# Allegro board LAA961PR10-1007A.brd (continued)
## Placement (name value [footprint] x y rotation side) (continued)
T21  PAD~D  [TPC12]  138.6 75.1 0 top
T22  PAD~D  [TPC12]  141.75 79.26 0 top
T27  PAD~D  [TPC12]  143.95 73.08 0 top
T28  PAD~D  [TPC12]  93.28 65.8 180 bottom
T29  PAD~D  [TPC12]  93.33 68.08 180 bottom
T30  PAD~D  [TPC12]  95.37 88.76 180 bottom
T31  PAD~D  [TPC12]  96.45 87.99 180 bottom
T33  PAD~D  [TPC12]  108.45 96.29 0 top
T34  PAD~D  [TPC12]  107.18 92.71 0 top
T35  PAD~D  [TPC12]  97.09 81.84 0 top
T74  PAD~D  [TPC12]  92.91 81.75 0 top
T75  PAD~D  [TPC12]  98.36 81.83 0 top
T76  PAD~D  [TPC12]  95.21 83.28 0 top
T77  PAD~D  [TPC12]  94.98 81.74 0 top
T88  PAD~D  [TPC12]  207.84 119.45 90 top
T89  PAD~D  [TPC12]  206.48 119.46 90 top
T96  PAD~D  [TPC12]  182.32 109.01 180 top
T97  PAD~D  [TPC12]  173.08 98.35 180 top
T98  PAD~D  [TPC12]  175.87 104.84 0 top
T99  PAD~D  [TPC12]  175.44 98.09 0 top
T108  PAD~D  [TPC12]  146.75 109.91 180 bottom
T109  PAD~D  [TPC12]  134.5 84.01 0 top
TL1  MHPC_NS692417  [MHPC_NS692417_24P]  268.27 131.63 0 bottom
UA1  -  [ALC3235-CG_MQFN48_6X6]  203.43 72.97 270 top
UC1  BDW-ULT-DDR3L_BGA1168  [BDW-ULT-DDR3L_BGA_1168P-T]  138.82 90.26 0 bottom
UC2  -  [W25Q64FVSSIQ_SO8]  182.19 76.25 270 bottom
UC3  -  [W25Q32FVSSIQ_SO8]  191.91 76.25 270 bottom
UC4  -  [74AHC1G09GW_TSSOP5]  162.06 85.54 270 bottom
UC5  TC7SH08FU_SSOP5~D  [TC7SH08FU_SSOP5]  161.8 80.68 180 bottom
UC6  TC7SH08FU_SSOP5~D  [TC7SH08FU_SSOP5]  159.33 80.26 180 bottom
UC7  -  [74CBTLV3126BQ_DHVQFN14_2P5X3]  63.6 67.13 90 top
UC8  -  [74AUP1G07GW_TSSOP5]  76 78.75 0 top
UD1  -  [74AUP1G07GW_TSSOP5]  96.6 13.14 180 top
UE1  ECE5048-LZY_DQFN132_11X11~D  [ECE5048-LZY_DQFN132_11X11]  176.99 105.34 270 top
UE2  -  [MEC5085-LZY_DQFN132_11X11]  211.07 88.25 90 top
UI2  SY6288D10CAC_MSOP8  [G547I2P81U_MSOP8]  240.06 121.66 90 bottom
UI3  -  [TPS2544RTER_WQFN16_3X3]  59.65 118.7 0 top
UI4  -  [PI3USB3102ZLEX_TQFN32_6X3]  127.73 128.96 0 top
UI5  -  [NX3DV221GM_XQFN10U10_2X1P55]  129.87 125.52 270 bottom
UI7  -  [PS8713BTQFN24GTR2_TQFN24_4X4]  222.6 82.96 270 top
UL1  WGI218LM-QQ89-B0_QFN48_6X6~D  [WGI217LM-QPN9-A2_QFN48_6X6]  206.15 112.27 0 top
UL2  -  [TC7SH08FU_SSOP5]  211.62 120.58 0 top
UL3  -  [TPS22966DPUR_SON14_2X3]  194.37 109.58 270 top
UL4  PI3L720ZHEX_TQFN42_9X3P5~D  [PI3L720ZHEX_TQFN42_9X3P5]  220.22 122.6 180 bottom
UN1  -  [LNG3DMTR_LGA16_3X3]  223.36 115.36 90 top
UR1  -  [OZ777FJ2LN_QFN48_6X6]  24.49 21.89 180 top
UV7  -  [PS8339BQFN56GTR2-A0_QFN56_7X7]  119.86 119.58 270 top
UV8  VMM3320BJGR_BGA168  [VMM3320BJGR_BGA_168P-NH]  155.72 108.16 90 bottom
UV9  W25X10CVSNIG_SO8  [W25X10BVSNIG_SO8]  151.92 97.84 90 bottom
UV10  -  [AP2330W-7_SC59-3]  99.63 126.61 90 bottom
UV11  PI3C3125LEX_TSSOP14~D  [PI3C3125LEX_TSSOP14]  133.83 121.17 90 bottom
UV12  PI3C3125LEX_TSSOP14~D  [PI3C3125LEX_TSSOP14]  159.79 107.09 0 bottom
UV13  -  [TPS22966DPUR_SON14_2X3]  140.15 101.2 180 bottom
UV24  -  [AP2821KTR-G1_SOT23-5]  77.39 122.96 270 top
UV501  -  [AP2337SA-7_SOT23-3]  253.2 126.48 90 top
UV502  PI3C3125LEX_TSSOP14~D  [PI3C3125LEX_TSSOP14]  236.54 119.82 0 top
UV600  -  [PS8338BQFN60GTR-A0_QFN60_5X9]  138.53 120.71 270 top
UZ1  AT97SC3205_TSSOP28~D  [AT97SC3205_TSSOP28]  182.18 61.1 270 top
UZ2  -  [TPS22966DPUR_SON14_2X3]  191 44.24 0 top
UZ5  -  [RT9818A-44GU3_SC70-3]  190.68 82.89 180 top
UZ6  TC7SH08FU_SSOP5~D  [TC7SH08FU_SSOP5]  186 88.42 90 top
UZ7  -  [TPS22966DPUR_SON14_2X3]  132.01 98.71 270 top
UZ8  -  [TPS22966DPUR_SON14_2X3]  202.26 33.33 90 top
UZ9  -  [TPS22966DPUR_SON14_2X3]  58 59.53 90 top
UZ10  TC7SH08FU_SSOP5~D  [TC7SH08FU_SSOP5]  186.3 115.69 0 top
UZ11  -  [TC7SH08FU_SSOP5]  176.11 111.12 270 top
YC1  32.768KHZ_12.5PF_9H03220008  [Y_9H03220008_2P]  143.85 62.09 0 bottom
YC2  24MHZ_12PF_X3G024000DC1H  [Y_X3G024000DC1H_4P]  127.34 99.03 90 top
YE1  32.768KHZ_12.5PF_Q13FC135000040  [Y_Q13FC135000040_2P]  207.65 83.22 270 top
YL1  25MHZ_18PF_7V25000034  [Y_7V25000034_4P]  209.71 104.34 90 top
YV2  27MHZ_12PF_X1E000021042600  [Y_X1E000021042600_4P]  141.76 103.92 90 bottom

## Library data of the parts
C33 PC5 PC10 PC101 PC102 PC200 PC201 PC205 PC303 PC305-PC308 PC401 PC404 PC515-PC518 PC704-PC709 PC714-PC717 PC723-PC725 PC807 PC900-PC904 PC913-PC917 = C_0805
C42 C43 C319 CA5-CA8 CA11 CA17 CA19 CA22-CA24 CA27 CA28 CA30 CA33 CA35 CA41 CA45 CA47 CA50 CC3 CC14 CC15 CC22 CC25 CC48 CC50 CC52 CC57 CC68-CC73 CC78 CC80 CC82 CC83 CC97 CC100 CC101 CD31 CD59 CD63 CD64 CE3-CE6 CE10-CE20 CE22-CE30 CE34-CE40 CE44-CE46 CI3-CI5 CI10 CI12 CI19 CI27-CI35 CI38 CI414-CI419 CL1-CL3 CL5 CL6 CL8-CL11 CL13-CL15 CL18 CL19 CL23-CL27 CN2 CN13-CN16 CN35-CN38 CR2-CR4 CR6 CR8 CR10 CR13 CR15 CR17 CR19 CR21-CR27 CR31 CR35 CV1-CV6 CV8 CV10 CV11 CV24 CV30 CV60-CV62 CV66 CV69 CV71-CV80 CV83-CV86 CV88 CV89 CV91-CV93 CV95-CV100 CV102-CV111 CV113-CV124 CV145-CV150 CV152 CV153 CV156 CV157 CV501-CV513 CV518 CV600-CV613 CZ1 CZ2 CZ4-CZ7 CZ9-CZ18 CZ20-CZ25 CZ27-CZ37 CZ39-CZ53 CZ55 CZ56 CZ58-CZ60 CZ62-CZ66 CZ68 PC3 PC4 PC105 PC106 PC203 PC206 PC212-PC215 PC300 PC304 PC311 PC400 PC402 PC403 PC501-PC504 PC506 PC511-PC514 PC520 PC521 PC702 PC703 PC711 PC713 PC718 PC719 PC726-PC728 PC732 PC737 PC741 PC805 PC809 PC810 PC817 = C_0402
C263 = C_0402: room: SIM
C294-C316 CE8 CE9 = C_0402: room: DOCK
C317 C318 CE7 = C_0603: room: DOCK
CA9 CA10 CA16 CA18 CA25 CA26 CA29 CA31 CA43 CA44 CA46 CA48 CA49 CA51-CA53 CC23 CC55 CC79 CC84 CC85 CD62 CE21 CE31 CE32 CI11 CI13 CI420 CL4 CL7 CL12 CL16 CL17 CL20 CL21 CN1 CR1 CR7 CR9 CR14 CR18 CR34 CV7 CV9 CV12 CV27 CV82 CV87 CV90 CV94 CV101 CZ19 CZ38 CZ54 PC1 PC9 PC11 PC100 PC109-PC111 PC114 PC117-PC119 PC204 PC208 PC209 PC211 PC301 PC302 PC309 PC310 PC500 PC505 PC507-PC510 PC700 PC701 PC710 PC712 PC721 PC722 PC729 PC813 PC815 PC816 = C_0603
CC1 CC2 CC4-CC13 CC17-CC21 CC24 CC26-CC28 CC35 CC37 CC40 CC43 CC44 CC49 CC53 CC54 CC58 CC59 CC61 CC65 CC66 = C_0402: room: CPU
CC29-CC34 CC36 CC47 CC51 CC56 CC60 CC62-CC64 = C_0603: room: CPU
CC39 = C_D2: room: CPU
CC41 = C_D3
CC42 = C_D3: room: CPU
CC67 = C_1206: room: CPU
CC77 CC81 CI1 CI8 = C_1206
CD1-CD11 CD21-CD27 CD30 CD32-CD44 CD54-CD58 CD60 = C_0402: room: MEMORY
CD12-CD19 CD28 CD29 CD45-CD52 CD61 = C_0603: room: MEMORY
CD20 CD53 = C_D3: room: MEMORY
CE1 = C_0603: room: EDP
CE2 = C_0402: room: EDP
CL22 = C_1808
CMOS1 = SHORTPADS: User Part Number: PART#; room: CPU
CZ57 = C_B2
D19 = RB751S40T1G_SOD523-2: room: DOCK
D20 = L30ESD24VC3-2_SOT23-3: room: DOCK
DA4 DA5 DE1 DZ1-DZ6 = RB751S40T1G_SOD523-2
DA6 DA7 = L03ESDL5V0CC3-2_SOT23-3
DI1 DI6 = L05ESDL5V0NA-4_SLP2510P8-10-9
DI2 DI3 DV4 PD5 = AZC199-02SPR7G_SOT23-3
DV1-DV3 PD815 PD817 = BAT54CW_SOT323-3
FD1-FD4 = FIDUCIAL_C40M80: room: LED
H1-H6 H12-H16 = H_2P8: room: LED
H7 = H_3P8
H8-H10 = H_3P8: room: LED
H11 H27 = H_2P8
H18 H19 = H_3P3
H20 = H_2P1N
H21 H22 = H_3P1: room: LED
H23 = H_2P1X2P6
JANT1 = ACES_50208-00801-003_8P
JAPS1 = ACES_50506-01841-P01_18P-NPM
JDEG1 = ACES_50521-01041-P01_10P: room: KBC
JDIMM1 JDIMM2 = BELLW_80001-1021_204P: room: MEMORY
JDOCK1 = JAE_WD2F144WB7-DT_144P-T: room: DOCK
JEDP1 = ACES_50398-04041-001_40P
JFAN1 = ACES_50271-0040N-001_4P: room: ETY-ROOM
JHDMI1 = LCN_AUF05-1922S10-0019_19P-T: room: ETY-ROOM
JIO1 = ACES_50506-03041-P01_30P: room: ETY-ROOM
JKBTP1 = ACES_50506-01641-P01_16P: room: ETY-ROOM
JLED1 = E-T_4260K-Q06N-23L_6P
JLOM1 = SANTA_130456-511_13P-T: room: LOM
JLPDE1 = HB_A531015-SCHR21_10P
JMDP1 = FOX_3V112M1-RA4A2-7H_20P
JNGFF1 = BELLW_80148-3221_67P-T
JNGFF2 = BELLW_80149-3221_67P
JRTC1 = TYCO_2-1775293-2_2P
JSATA1 = E-T_0870K-F20C-22L_20P: room: HDD
JSD1 = T-SOL_156-2000302608_19P_NR-S: room: OZ777
JSIM1 = T-SOL_159-1000302602_10P-T: room: ETY-ROOM
JSPI1 = E-T_6700K-Y20N-00L_20P
JSPK1 = E-T_4280K-F04N-05L_4P: room: ETY-ROOM
JTAG1 = SHORTPADS: User Part Number: PART#; room: KBC
JUSB1 JUSB2 = TAITW_PUBAU4-09FLBS1FF4H0_9P: room: ETY-ROOM
JUSH1 = E-T_6705K-Y20N-00L_20P: room: ETY-ROOM
JXDP1 = SAMTE_BSH-030-01-L-D-A_60P: room: CPU
LA5 = MURAT_BLM15PX600SN1D_2P
LA6-LA9 = MURAT_BLM15PX330SN1D_2P
LC1-LC5 = MURAT_LQM2MPN2R2NG0L_2P: room: CPU
LED5 LED6 = LED_LTW-193ZDS5_2P: room: ETY-ROOM
LED7 = LED_LTW-295DSKS-5A_4P: room: ETY-ROOM
LI1-LI4 LI8 LI9 LV3 LV6 LV10 LV12 LV27 LZ1 = MURAT_DLW21HN900HQ2L_4P
LL1 = TAIYO_BRC2012T4R7MD_2P
LV1 = MURAT_BLM15BB221SN1D_2P
LV22-LV25 = MURAT_BLM15PX181SN1D_2P
PBATT1 = ALLTO_C144LS-109A9-L_9P-T
PC113 PC115 = C_APXK6R3ARA221MF451
PC207 PC966 = C_D2
PC519 = C_D
PD1 PD2 = TVNST52302AB0_SOT523-3
PD3 = BAS40-05W_SC70-3
PD4 = RB751V-40_SOD323-2
PD702 PD704 PD705 PD813 = SDMK0340L-7-F_SOD323-2
PD800 PD808 = PDS5100H-13_POWERDI5-3
PH500 PH501 PR1 PR2 PR7-PR15 PR17 PR18 PR100-PR102 PR104-PR107 PR114 PR201 PR205 PR206 PR209 PR303 PR306-PR310 PR315 PR400-PR403 PR500-PR516 PR518 PR521 PR523-PR525 PR527-PR529 PR535 PR703 PR706 PR707 PR710 PR711 PR713 PR715 PR722 PR725 PR729 PR737 PR738 PR740 PR745 PR788 PR799 PR810 PR813-PR816 PR818 PR819 PR822 PR826-PR830 PR844 PR846 PR858 PR863 PR864 PR874 R6 R41 R273 RA5-RA9 RA12-RA14 RA17 RA18 RA21 RA24-RA32 RA38 RA44 RC21 RC27 RC34 RC62 RC66 RC68 RC80 RC92 RC98 RC121 RC123 RC124 RC126 RC128 RC130 RC132 RC136 RC139 RC141 RC142 RC156 RC164 RC171 RC174 RC176 RC178-RC180 RC184-RC189 RC191 RC192 RC194 RC195 RC197-RC199 RC201 RC202 RC204 RC207-RC209 RC211 RC213 RC216 RC224-RC229 RC231 RC247 RC300 RC302-RC305 RD2 RD4 RD9 RD12-RD14 RD18-RD25 RE8-RE12 RE17 RE20 RE21 RE24-RE27 RE31 RE33 RE35-RE37 RE42 RE43 RE48 RE51 RE55-RE58 RE60 RE62-RE75 RE77-RE79 RE81-RE83 RE85-RE88 RE274 RE276 RE277 RE280 RE281 RE283 RE284 RI4 RI13 RI14 RI16 RI18-RI20 RI22-RI25 RI34-RI38 RL1 RL2 RL4-RL6 RL9 RL11-RL20 RL29 RL30 RN1-RN7 RR1 RR2 RR5 RR6 RR8 RR11 RR15 RV1-RV9 RV14 RV15 RV50-RV52 RV54-RV58 RV60-RV68 RV73-RV91 RV100 RV501-RV505 RV507-RV509 RV516-RV519 RV550 RV551 RV554 RV555 RV600-RV620 RV701 RV702 RZ5 RZ8-RZ10 RZ14-RZ16 RZ18 RZ19 RZ21 RZ22 RZ24-RZ41 RZ43 RZ44 RZ56 = R_0402
PJP1 PJP13 PJP21 PJP22 PJP32 PJP100-PJP102 PJP203 PJP204 PJP300 PJP500 = JUMP_43X118
PJP5 = JUMP_43X39: room: TPM
PJP6 = JUMP_43X79: room: SIO
PJP9 PJP200 PJP302 = JUMP_43X79
PJP10-PJP12 PJP14-PJP17 PJP19 PJP23-PJP29 PJP36 PJP51 PJP66 PJP201 PJP202 PJP400 PJP401 PJP701 = JUMP_43X39
PJP700 = JUMP_43X118-NPM
PJPDC1 = ACES_50299-0050N-001_5P
PL1 PL2 PL4 = TAIYO_FBMJ4516HS720NT_2P
PL3 = MURAT_BLM15AG102SN1D_2P
PL100 = L_5X5X3_M_2P-NPM
PL101 PL102 PL200 = PANAS_ETQP3W2R2WFN_2P
PL301 PL700 = L_5X5X3_M_2P
PL500 = PANAS_ETQP4LR15AFM_4P
PL501 = FBMA-L11-453215800LMA90T_2P-NPM
PL701 = TOKO_FDVE1040-H-3R3M-P3_2P
PQ1 = FDN338P_NL_SOT23-3
PQ2 = FDV301N-G_SOT23-3
PQ3 = MMST3904-7-F_SOT323-3
PQ4 PQ826 = FDMC6679AZ_MLP8-5
PQ6 = IMD2AT-108_SC74-6
PQ100 PQ101 PQ200 = SIS412DN-T1-GE3_POWERPAK8-5
PQ102 PQ103 PQ201 = SI7716ADN-T1-GE3_POWERPAK8-5
PQ700 PQ800 = SI4835DDY-T1-GE3_SO8
PQ701 PQ702 PQ814 = NTR4502PT1G_SOT23-3
PQ703 = NTGD4161PT1G_TSOP6
PQ705 = AON6970_DFN5X6D-8-7
PQ712 PQ816 PQ832 = DMN65D8LW-7_SOT323-3
PQ806 PQ813 PQ817 = DMN65D8LDW-7_SOT363-6
PQ810 PQ815 = FDS6679AZ-G_SO8
PQ829 = SI2301CDS-T1-GE3_SOT23-3
PR6 PR103 PR108 PR113 PR207 PR210 PR313 PR520 PR531 PR532 PR534 PR536 PR539 PR700 PR702 PR704 PR705 PR709 PR714 PR716-PR718 PR720 PR728 PR743 PR811 PR812 PR842 PR843 PR845 PR848 PR850 PR851 PR853-PR855 PR857 PR859 PR895 RA35-RA37 RA45 RC26 RC32 RC65 RC77 RC212 RC217 RC219 RC301 RD15 RD16 RD27 RD28 RE32 RE61 RE275 RE279 RE282 RL3 RL7 RL10 RR3 RR4 RZ17 RZ42 RZ50 RZ51 RZ57 = R0402_0OHM
PR16 PR835 = R_0805
PR109 PR110 PR200 PR202 PR204 PR312 PR517 PR519 PR526 PR712 PR723 PR831 PR832 PR838 PR847 PR860 RC196 RL21-RL28 RZ46 = R_0603
PR111 PR112 PR203 PR305 PR522 PR708 PR726 RZ52 = R_1206
PR701 PR721 = R_1206_4P-D
PRP2 RPC1-RPC12 RPC14-RPC21 RPE2-RPE10 RPV1 RPV2 = RP_0804_8P4R
PT1-PT3 T8 T9 T88 T89 T96 T99 T108 T109 = TPC12
PU1 = TS5A63157DCKR_SC70-6
PU100 = TPS51285BRUKR_QFN20_3X3
PU200 = RT8207MZQW_WQFN20_3X3
PU300 = SYX198DQNC_QFN10_3X3
PU400 = APL5930KAI-TRG_SO8
PU500 = TPS51622RSM_QFN32_4X4
PU501 = CSD97374CQ4M_SON8_3P5X4P5
PU700 = BQ24715URUYR_WQFN28_4X4
PU800 = CD3301RHHR_QFN36_6X6
PU804 PU806 UC5 UC6 UL2 UZ6 UZ10 UZ11 = TC7SH08FU_SSOP5
QA1 QV2 QV7 QV9 QV10 QV501 QV502 = L2N7002WT1G_SC-70-3
QA2 QA3 QE2 QL1 QL2 QN1 QV700 QZ2 QZ3 QZ5 QZ7 QZ10 QZ11 QZ14 = DMN66D0LDW-7_SOT363-6
QC1 = DMN66D0LDW-7_SOT363-6: room: CPU
QD1 = L2N7002WT1G_SC-70-3: room: MEMORY
QE3-QE7 = MMBT3904WT1G_SC70-3
QV1 = AO6405_TSOP6
QV8 QZ1 = LP2301ALT1G_SOT23-3
QZ4 QZ9 QZ12 = DDTA114EUA-7-F_SOT323-3
QZ6 = SI3456DDV-T1-GE3_TSOP6
R252-R268 R271 R272 RE5 = R_0402: room: DOCK
RA3 RA4 RL8 RZ47 RZ53 = R0603_0OHM
RA39 = R0805_0OHM
RC1 RC2 RC7-RC11 RC17-RC20 RC22 RC23 RC25 RC29 RC31 RC33 RC38 RC55 RC61 RC63 RC67 RC69 RC70 RC72 RC74 RC78 RC79 RC81 RC82 RC91 RC95 RC99 RC102 RC103 RC106 RC109 RC112-RC120 RC122 RC125 RC127 RC129 RC131 RC133 RC140 RC149 RC152 RC153 RC155 RC158 RC160 RC163 RC175 RC183 RC190 RC193 RC218 RC230 RC240-RC243 RC245 = R_0402: room: CPU
RC4 RC30 RC35 RC50 RC87-RC89 RC161 = R0402_0OHM: room: CPU
RD3 = R0402_0OHM: room: MEMORY
RD5-RD7 RD10 RD11 = R_0402: room: MEMORY
ST1-ST3 = CLIP_C5P5
SW1 = SW_SS3-CMFTQR9_3P
SW2 = SW_SKRBAAE010_4P
T10-T16 T21 T22 T27-T31 T33-T35 T74-T77 = TPC12: room: CPU
T97 T98 = TPC12: room: SIO
TL1 = MHPC_NS692417_24P
UA1 = ALC3235-CG_MQFN48_6X6
UC1 = BDW-ULT-DDR3L_BGA_1168P-T: room: CPU
UC2 = W25Q64FVSSIQ_SO8: room: CPU
UC3 = W25Q32FVSSIQ_SO8: room: CPU
UC4 = 74AHC1G09GW_TSSOP5: room: CPU
UC7 = 74CBTLV3126BQ_DHVQFN14_2P5X3
UC8 UD1 = 74AUP1G07GW_TSSOP5
UE1 = ECE5048-LZY_DQFN132_11X11
UE2 = MEC5085-LZY_DQFN132_11X11
UI2 = G547I2P81U_MSOP8
UI3 = TPS2544RTER_WQFN16_3X3
UI4 = PI3USB3102ZLEX_TQFN32_6X3
UI5 = NX3DV221GM_XQFN10U10_2X1P55
UI7 = PS8713BTQFN24GTR2_TQFN24_4X4
UL1 = WGI217LM-QPN9-A2_QFN48_6X6
UL3 UV13 UZ2 UZ7-UZ9 = TPS22966DPUR_SON14_2X3
UL4 = PI3L720ZHEX_TQFN42_9X3P5
UN1 = LNG3DMTR_LGA16_3X3
UR1 = OZ777FJ2LN_QFN48_6X6
UV7 = PS8339BQFN56GTR2-A0_QFN56_7X7
UV8 = VMM3320BJGR_BGA_168P-NH
UV9 = W25X10BVSNIG_SO8
UV10 = AP2330W-7_SC59-3
UV11 UV12 UV502 = PI3C3125LEX_TSSOP14
UV24 = AP2821KTR-G1_SOT23-5
UV501 = AP2337SA-7_SOT23-3
UV600 = PS8338BQFN60GTR-A0_QFN60_5X9
UZ1 = AT97SC3205_TSSOP28
UZ5 = RT9818A-44GU3_SC70-3
YC1 = Y_9H03220008_2P: room: CPU
YC2 = Y_X3G024000DC1H_4P: room: CPU
YE1 = Y_Q13FC135000040_2P
YL1 = Y_7V25000034_4P
YV2 = Y_X1E000021042600_4P

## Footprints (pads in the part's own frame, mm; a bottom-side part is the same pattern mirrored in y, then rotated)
74AHC1G09GW_TSSOP5
  oval 0.381x1.346 smd: 1(0,0) 2(0.65,0) 3(1.3,0) 4(1.3,1.79) 5(0,1.79)
74AUP1G07GW_TSSOP5
  oval 0.381x1.346 smd: 1(0,0) 2(0.65,0) 3(1.3,0) 4(1.3,1.79) 5(0,1.79)
74CBTLV3126BQ_DHVQFN14_2P5X3
  oval 1.041x0.254 smd: 1(0,0) 7(2.95,0) 8(2.95,0.5) 14(0,0.5)
  oval 0.254x1.041 smd: 2(0.475,-0.975) 3(0.975,-0.975) 4(1.475,-0.975) 5(1.975,-0.975) 6(2.475,-0.975) 9(2.475,1.475) 10(1.975,1.475) 11(1.475,1.475) 12(0.975,1.475) 13(0.475,1.475)
  rect 1.499x0.991 smd: 15(1.475,0.25)
ACES_50208-00801-003_8P
  oval 0.508x0.991 smd: 1(0,0) 2(-0.8,0) 3(-1.6,0) 4(-2.4,0) 5(-3.2,0) 6(-4,0) 7(-4.8,0) 8(-5.6,0)
  rect 1.194x1.702 smd: 9(1.3,-1.95) 10(-6.9,-1.95)
ACES_50271-0040N-001_4P
  oval 0.787x1.6 smd: 1(0,0) 2(-1.25,0) 3(-2.5,0) 4(-3.75,0)
  rect 2.108x2.997 smd: 5(2.55,-2.9) 6(-6.3,-2.9)
ACES_50299-0050N-001_5P
  round 1.803 hole 1.803 unplated: (-0.2,5.15) (8.2,5.15)
  oval 0.889x2.311 smd: 1(0,0) 2(2,0) 3(4,0) 4(6,0) 5(8,0)
ACES_50398-04041-001_40P
  oval 0.254x1.295 smd: 1(0,0) 2(0.5,0) 3(1,0) 4(1.5,0) 5(2,0) 6(2.5,0) 7(3,0) 8(3.5,0) 9(4,0) 10(4.5,0) 11(5,0) 12(5.5,0) 13(6,0) 14(6.5,0) 15(7,0) 16(7.5,0) 17(8,0) 18(8.5,0) 19(9,0) 20(9.5,0) 21(10,0) 22(10.5,0) 23(11,0) 24(11.5,0) 25(12,0) 26(12.5,0) 27(13,0) 28(13.5,0) 29(14,0) 30(14.5,0) 31(15,0) 32(15.5,0) 33(16,0) 34(16.5,0) 35(17,0) 36(17.5,0) 37(18,0) 38(18.5,0) 39(19,0) 40(19.5,0)
  rect 1.194x3.2 smd: 41(-2.4,1.95) 45(21.9,1.95)
  rect 2.311x1.295 smd: 42(0.85,3.9) 43(9.75,3.9) 44(18.65,3.9)
ACES_50506-01641-P01_16P
  oval 0.305x0.889 smd: 1(0,0) 2(0.5,0) 3(1,0) 4(1.5,0) 5(2,0) 6(2.5,0) 7(3,0) 8(3.5,0) 9(4,0) 10(4.5,0) 11(5,0) 12(5.5,0) 13(6,0) 14(6.5,0) 15(7,0) 16(7.5,0)
  rect 0.991x2.007 smd: 17(9.6,-3.05) 18(-2.1,-3.05)
ACES_50506-01841-P01_18P-NPM
  oval 0.305x0.889 smd: 1(0,0) 2(0.5,0) 3(1,0) 4(1.5,0) 5(2,0) 6(2.5,0) 7(3,0) 8(3.5,0) 9(4,0) 10(4.5,0) 11(5,0) 12(5.5,0) 13(6,0) 14(6.5,0) 15(7,0) 16(7.5,0) 17(8,0) 18(8.5,0)
  rect 0.991x2.007 smd: 19(-2.1,-3.05) 20(10.6,-3.05)
ACES_50506-03041-P01_30P
  oval 0.305x0.889 smd: 1(0,0) 2(0.5,0) 3(1,0) 4(1.5,0) 5(2,0) 6(2.5,0) 7(3,0) 8(3.5,0) 9(4,0) 10(4.5,0) 11(5,0) 12(5.5,0) 13(6,0) 14(6.5,0) 15(7,0) 16(7.5,0) 17(8,0) 18(8.5,0) 19(9,0) 20(9.5,0) 21(10,0) 22(10.5,0) 23(11,0) 24(11.5,0) 25(12,0) 26(12.5,0) 27(13,0) 28(13.5,0) 29(14,0) 30(14.5,0)
  rect 0.991x2.007 smd: 31(-2.1,-3.05) 32(16.6,-3.05)
ACES_50521-01041-P01_10P
  oval 0.305x0.787 smd: 1(0,0) 2(0.5,0) 3(1,0) 4(1.5,0) 5(2,0) 6(2.5,0) 7(3,0) 8(3.5,0) 9(4,0) 10(4.5,0)
  rect 0.406x0.787 smd: 11(-1,-2.5) 12(5.5,-2.5)
ALC3235-CG_MQFN48_6X6
  oval 0.203x0.889 smd: 1(0,0) 2(0.4,0) 3(0.8,0) 4(1.2,0) 5(1.6,0) 6(2,0) 7(2.4,0) 8(2.8,0) 9(3.2,0) 10(3.6,0) 11(4,0) 12(4.4,0) 25(4.4,6.1) 26(4,6.1) 27(3.6,6.1) 28(3.2,6.1) 29(2.8,6.1) 30(2.4,6.1) 31(2,6.1) 32(1.6,6.1) 33(1.2,6.1) 34(0.8,6.1) 35(0.4,6.1) 36(0,6.1)
  oval 0.889x0.203 smd: 13(5.25,0.85) 14(5.25,1.25) 15(5.25,1.65) 16(5.25,2.05) 17(5.25,2.45) 18(5.25,2.85) 19(5.25,3.25) 20(5.25,3.65) 21(5.25,4.05) 22(5.25,4.45) 23(5.25,4.85) 24(5.25,5.25) 37(-0.85,5.25) 38(-0.85,4.85) 39(-0.85,4.45) 40(-0.85,4.05) 41(-0.85,3.65) 42(-0.85,3.25) 43(-0.85,2.85) 44(-0.85,2.45) 45(-0.85,2.05) 46(-0.85,1.65) 47(-0.85,1.25) 48(-0.85,0.85)
  rect 4.394x4.394 smd: 49(2.2,3.05)
ALLTO_C144LS-109A9-L_9P-T
  round 1.803 hole 1.194: 1(0,0) 2(2,0) 3(4,0) 4(6,0) 5(8,0) 6(10,0) 7(12,0) 8(14,0) 9(16,0)
  oval 1.6x3.404 hole 0.991x2.794: 10(19.125,0.25) 11(-3.125,0.25)
AO6405_TSOP6
  oval 0.508x1.473 smd: 1(0,0) 2(0.95,0) 3(1.9,0) 4(1.9,2.35) 5(0.95,2.35) 6(0,2.35)
AON6970_DFN5X6D-8-7
  oval 0.66x0.635 smd: 1(0,0) 3(3.81,5.67) 4(2.54,5.67) 5(1.27,5.67) 6(0,5.67)
  custom 0.485x0.485 smd: 2(1.905,0.655)
  rect 3.988x2.667 smd: 7(1.905,3.62)
AP2330W-7_SC59-3
  oval 0.787x0.991 smd: 1(0,0) 2(-0.95,-2.4) 3(0.95,-2.4)
AP2337SA-7_SOT23-3
  oval 1.016x1.524 smd: 1(0,0) 2(0.965,2.083) 3(-0.965,2.083)
AP2821KTR-G1_SOT23-5
  oval 0.508x0.787 smd: 1(0,0) 2(0.95,0) 3(1.9,0) 4(1.9,2.4) 5(0,2.4)
APL5930KAI-TRG_SO8
  oval 0.635x1.854 smd: 1(0,0) 2(1.27,0) 3(2.54,0) 4(3.81,0) 5(3.81,5.165) 6(2.54,5.165) 7(1.27,5.165) 8(0,5.165)
  rect 2.87x2.489 smd: 9(1.905,2.582)
AT97SC3205_TSSOP28
  oval 0.381x1.626 smd: 1(0,0) 2(0.65,0) 3(1.3,0) 4(1.95,0) 5(2.6,0) 6(3.25,0) 7(3.9,0) 8(4.55,0) 9(5.2,0) 10(5.85,0) 11(6.5,0) 12(7.15,0) 13(7.8,0) 14(8.45,0) 15(8.45,5.8) 16(7.8,5.8) 17(7.15,5.8) 18(6.5,5.8) 19(5.85,5.8) 20(5.2,5.8) 21(4.55,5.8) 22(3.9,5.8) 23(3.25,5.8) 24(2.6,5.8) 25(1.95,5.8) 26(1.3,5.8) 27(0.65,5.8) 28(0,5.8)
AZC199-02SPR7G_SOT23-3
  oval 1.016x1.524 smd: 1(0,0) 2(0.965,2.083) 3(-0.965,2.083)
BAS40-05W_SC70-3
  oval 0.508x0.559 smd: 1(0,0) 2(-0.65,-1.85) 3(0.65,-1.85)
BAT54CW_SOT323-3
  oval 0.61x0.559 smd: 1(0,0) 2(-0.65,-1.85) 3(0.65,-1.85)
BDW-ULT-DDR3L_BGA_1168P-T
  round 0.508 smd: A3(-1.137,0) A62(-38.036,0) AW1(0,22.042) AW63(-38.628,22.057) AY2(-0.543,22.628) AY62(-38.062,22.628) B2(-0.508,0.508) B63(-38.628,0.592) C1(0,1.137)
  round 0.381 smd: A4(-1.894,0) A5(-2.554,0) A6(-3.75,0) A59(-35.9,0) A60(-36.726,0) A61(-37.386,0) AA9(-5.032,11.576) AA21(-11.688,11.489) AA23(-13.115,11.489) AA58(-35.377,11.33) AB10(-5.476,12.053) AB20(-11.18,11.896) AB21(-11.688,12.302) AB22(-12.607,11.896) AB23(-13.115,12.302) AB57(-35.057,11.98) AC9(-5.032,12.529) AC20(-11.18,12.709) AC22(-12.607,12.709) AC58(-35.377,12.63) AD10(-5.476,13.005) AD21(-11.688,13.115) AD23(-13.115,13.115) AD57(-35.057,13.28) AE9(-5.032,13.481) AE10(-5.476,13.958) AE20(-11.18,13.521) AE21(-11.688,13.928) AE22(-12.607,13.521) AE23(-13.115,13.928) AE58(-35.377,13.931) AF9(-5.032,14.434) AF11(-6.059,14.282) AF12(-6.872,14.282) AF14(-7.685,14.282) AF15(-8.497,14.282) AF17(-9.31,14.282) AF18(-10.123,14.282) AF20(-10.936,14.282) AF22(-12.607,14.334) AG10(-5.653,14.79) AG11(-6.465,14.79) AG13(-7.278,14.79) AG14(-8.091,14.79) AG16(-8.904,14.79) AG17(-9.717,14.79) AG19(-10.529,14.79) AG20(-11.342,14.79) AG23(-13.115,14.741) AG57(-35.057,14.581) AG58(-35.692,15.009) AH22(-12.607,15.147) AH24(-13.92,15.289) AH26(-15.22,15.289) AH28(-16.521,15.289) AH30(-17.821,15.289) AH32(-19.122,15.289) AH34(-20.422,15.289) AH36(-21.723,15.289) AH38(-23.023,15.289) AH40(-24.324,15.289) AH42(-25.624,15.289) AH44(-26.925,15.289) AH46(-28.225,15.289) AH49(-29.526,15.289) AH51(-30.826,15.289) AH53(-32.127,15.289) AH55(-33.427,15.289) AH57(-34.728,15.289) AJ23(-13.115,15.553) AJ25(-14.57,15.614) AJ27(-15.871,15.614) AJ29(-17.171,15.614) AJ31(-18.472,15.614) AJ33(-19.772,15.614) AJ35(-21.073,15.614) AJ37(-22.373,15.614) AJ39(-23.674,15.614) AJ41(-24.974,15.614) AJ43(-26.275,15.614) AJ45(-27.575,15.614) AJ47(-28.875,15.614) AJ50(-30.176,15.614) AJ52(-31.476,15.614) AJ54(-32.777,15.614) AJ56(-34.077,15.614) AJ58(-35.378,15.614) AT1(0,19.997) AT63(-38.628,19.848) AU1(0,20.657) AU63(-38.628,20.673) AV1(0,21.318) AV2(-0.66,21.308) AV62(-37.978,21.318) AV63(-38.628,21.333) AW2(-0.66,21.968) AW3(-1.321,21.968) AW61(-37.328,21.978) AW62(-37.978,21.978) AY3(-1.267,22.628) AY4(-1.928,22.628) AY5(-2.588,22.628) AY59(-36.088,22.628) AY60(-36.748,22.628) AY61(-37.409,22.628) B3(-1.259,0.65) B61(-37.315,0.66) B62(-37.978,0.724) C2(-0.65,1.259) C62(-37.978,1.384) C63(-38.628,1.316) D1(0,1.861) D63(-38.628,1.976) E1(0,2.522) E23(-13.333,2.601) E25(-14.714,2.601) E27(-15.84,2.601) E29(-17.221,2.601) E31(-18.348,2.601) E33(-19.729,2.601) E35(-20.855,2.601) E37(-22.236,2.601) E39(-23.363,2.601) E41(-24.744,2.601) E43(-25.87,2.601) E45(-27.251,2.601) E47(-28.378,2.601) E49(-29.759,2.601) E51(-30.885,2.601) E53(-32.266,2.601) E55(-33.393,2.601) E57(-34.774,2.601) E63(-38.628,2.647) F1(0,3.436) F22(-12.717,3.058) F24(-14.023,3.126) F26(-15.277,3.126) F28(-16.531,3.126) F30(-17.785,3.126) F32(-19.038,3.126) F34(-20.292,3.126) F36(-21.546,3.126) F38(-22.8,3.126) F40(-24.053,3.126) F42(-25.307,3.126) F44(-26.561,3.126) F46(-27.815,3.126) F48(-29.068,3.126) F50(-30.322,3.126) F52(-31.576,3.126) F54(-32.83,3.126) F56(-34.083,3.126) F58(-35.377,3.126) G22(-12.607,3.768) G23(-13.333,3.451) G25(-14.714,3.451) G27(-15.84,3.451) G29(-17.221,3.451) G31(-18.348,3.451) G33(-19.729,3.451) G35(-20.855,3.451) G37(-22.236,3.451) G39(-23.363,3.451) G41(-24.744,3.451) G43(-25.87,3.451) G45(-27.251,3.451) G47(-28.378,3.451) G49(-29.759,3.451) G51(-30.885,3.451) G53(-32.266,3.451) G55(-33.393,3.451) G57(-34.774,3.451) H22(-12.607,4.581) H23(-13.115,4.174) H57(-35.057,4.101) J22(-12.607,5.393) J23(-13.115,4.987) J58(-35.377,4.827) K9(-5.032,5.861) K10(-5.935,5.7) K12(-6.888,5.7) K14(-7.84,5.7) K16(-8.793,5.7) K18(-9.745,5.7) K19(-10.698,5.7) K21(-11.65,5.7) K23(-13.115,5.8) K57(-35.057,5.478) L10(-5.476,6.338) L11(-6.412,6.144) L13(-7.364,6.144) L15(-8.317,6.144) L17(-9.269,6.144) L18(-10.222,6.144) L20(-11.18,6.206) L22(-12.607,6.206) L58(-35.377,6.128) M9(-5.032,6.814) M20(-11.18,7.019) M21(-11.688,6.613) M22(-12.607,7.019) M23(-13.115,6.613) M57(-35.057,6.778) N10(-5.476,7.29) N21(-11.688,7.425) N23(-13.115,7.425) N58(-35.377,7.428) P9(-5.032,7.766) P20(-11.18,7.832) P22(-12.607,7.832) P57(-35.057,8.078) R10(-5.476,8.243) R20(-11.18,8.645) R21(-11.688,8.238) R22(-12.607,8.645) R23(-13.115,8.238) T9(-5.032,8.719) T21(-11.688,9.051) T23(-13.115,9.051) T58(-35.377,8.729) U9(-5.032,9.671) U10(-5.476,9.195) U20(-11.18,9.457) U22(-12.607,9.457) U57(-35.057,9.379) V10(-5.476,10.148) V21(-11.688,9.864) V23(-13.115,9.864) V58(-35.377,10.029) W9(-5.032,10.624) W20(-11.18,10.27) W21(-11.688,10.677) W22(-12.607,10.27) W23(-13.115,10.677) W57(-35.057,10.679) Y10(-5.476,11.1) Y20(-11.18,11.083) Y22(-12.607,11.083)
  round 0.305 smd: A8(-4.538,0) A9(-5.452,0) A11(-6.367,0) A12(-7.116,0) A14(-8.03,0) A15(-8.945,0) A17(-9.694,0) A18(-10.608,0) A20(-11.523,0) A21(-12.272,0) A23(-13.186,0) A24(-14.023,0.325) A25(-14.714,0) A27(-15.84,0) A28(-16.531,0.325) A29(-17.221,0) A31(-18.348,0) A32(-19.038,0.325) A33(-19.729,0) A35(-20.855,0) A36(-21.546,0.325) A37(-22.236,0) A39(-23.363,0) A40(-24.053,0.325) A41(-24.744,0) A43(-25.87,0) A44(-26.561,0.325) A45(-27.251,0) A47(-28.378,0) A48(-29.068,0.325) A49(-29.759,0) A51(-30.885,0) A52(-31.576,0.325) A53(-32.266,0) A55(-33.393,0) A56(-34.083,0.325) A57(-34.774,0) AA1(0,11.717) AA2(-0.65,11.717) AA3(-1.3,11.678) AA4(-1.951,11.678) AA59(-36.027,11.638) AA60(-36.678,11.638) AA61(-37.328,11.638) AA62(-37.978,11.676) AA63(-38.628,11.676) AB5(-2.637,12.053) AB6(-3.287,12.053) AB7(-3.937,12.053) AB8(-4.587,12.053) AC1(0,12.466) AC2(-0.65,12.466) AC3(-1.3,12.504) AC4(-1.951,12.504) AC59(-36.027,12.464) AC60(-36.678,12.464) AC61(-37.328,12.464) AC62(-37.978,12.426) AC63(-38.628,12.426) AD1(0,13.215) AD2(-0.65,13.215) AD3(-1.3,13.177) AD4(-1.951,13.177) AD5(-2.637,13.005) AD6(-3.287,13.005) AD7(-3.937,13.005) AD8(-4.587,13.005) AD59(-36.027,13.137) AD60(-36.678,13.137) AD61(-37.328,13.137) AD62(-37.978,13.175) AD63(-38.628,13.175) AE5(-2.637,13.958) AE6(-3.287,13.958) AE7(-3.937,13.958) AE8(-4.587,13.958) AE59(-36.027,13.962) AE60(-36.678,13.962) AE61(-37.328,13.962) AE62(-37.978,13.924) AE63(-38.628,13.924) AF1(0,13.964) AF2(-0.65,13.964) AF3(-1.3,14.003) AF4(-1.951,14.003) AG1(0,14.714) AG2(-0.65,14.714) AG3(-1.3,14.676) AG4(-1.951,14.676) AG5(-2.637,14.91) AG6(-3.287,14.91) AG7(-3.937,14.91) AG8(-4.587,14.91) AG21(-11.955,15.122) AG60(-36.352,14.602) AG61(-37.003,14.602) AG62(-37.653,14.602) AG63(-38.303,14.602) AH1(0,15.463) AH2(-0.65,15.463) AH3(-1.3,15.501) AH4(-1.951,15.501) AH10(-5.653,15.476) AH11(-6.465,15.476) AH13(-7.278,15.476) AH14(-8.091,15.476) AH16(-8.904,15.476) AH17(-9.717,15.476) AH19(-10.529,15.476) AH20(-11.342,15.476) AH60(-36.678,15.278) AH61(-37.328,15.278) AH62(-37.978,15.278) AH63(-38.628,15.278) AJ5(-2.637,15.863) AJ6(-3.287,15.863) AJ7(-3.937,15.863) AJ8(-4.587,15.863) AJ10(-5.653,16.126) AJ11(-6.465,16.126) AJ13(-7.278,16.126) AJ14(-8.091,16.126) AJ60(-36.352,15.954) AJ61(-37.003,15.954) AJ62(-37.653,15.954) AJ63(-38.303,15.954) AK1(0,16.212) AK2(-0.65,16.212) AK3(-1.3,16.174) AK4(-1.951,16.174) AK8(-4.303,16.451) AK18(-9.848,16.266) AK20(-10.801,16.266) AK21(-11.753,16.266) AK60(-36.678,16.523) AK61(-37.328,16.523) AK62(-37.978,16.629) AK63(-38.628,16.629) AL1(0,16.962) AL2(-0.65,16.962) AL3(-1.3,17) AL4(-1.951,17) AL5(-2.901,16.776) AL7(-3.739,16.776) AL8(-4.303,17.101) AL10(-5.658,16.776) AL11(-6.221,17.101) AL13(-7.576,16.776) AL15(-8.14,17.101) AL17(-9.222,16.583) AL18(-9.848,16.916) AL20(-10.801,16.916) AL21(-11.753,16.916) AL22(-12.706,16.916) AL23(-13.529,16.916) AL25(-14.504,16.916) AL26(-15.456,16.916) AL28(-16.409,16.916) AL29(-17.361,16.916) AL31(-18.26,16.591) AL32(-18.824,16.916) AL33(-19.726,16.916) AL35(-20.729,16.916) AL36(-21.58,16.916) AL38(-22.634,16.916) AL39(-23.542,16.591) AL40(-24.131,16.916) AL42(-24.944,16.916) AL43(-25.897,16.916) AL45(-26.874,16.916) AL46(-27.802,16.916) AL48(-28.856,16.916) AL49(-29.757,16.916) AL51(-30.761,16.916) AL52(-31.583,16.916) AL54(-32.61,16.916) AL55(-33.562,16.916) AL57(-34.509,16.916) AL58(-35.408,16.916) AL60(-36.352,17.169) AL61(-37.003,17.169) AM1(0,17.711) AM2(-0.65,17.711) AM3(-1.3,17.673) AM4(-1.951,17.673) AM5(-2.901,17.426) AM7(-3.739,17.426) AM8(-4.303,17.752) AM10(-5.658,17.426) AM11(-6.221,17.752) AM13(-7.576,17.426) AM15(-8.14,17.752) AM17(-9.222,17.233) AM18(-9.848,17.567) AM20(-10.801,17.567) AM21(-11.753,17.567) AM22(-12.706,17.567) AM23(-13.529,17.567) AM25(-14.504,17.567) AM26(-15.456,17.567) AM28(-16.409,17.567) AM29(-17.361,17.567) AM31(-18.26,17.242) AM32(-18.824,17.567) AM33(-19.726,17.567) AM35(-20.729,17.567) AM36(-21.58,17.567) AM38(-22.634,17.567) AM40(-24.131,17.567) AM42(-24.944,17.567) AM43(-25.897,17.567) AM45(-26.874,17.567) AM46(-27.802,17.567) AM48(-28.856,17.567) AM49(-29.757,17.567) AM51(-30.761,17.567) AM52(-31.583,17.567) AM54(-32.61,17.567) AM55(-33.562,17.567) AM57(-34.509,17.567) AM58(-35.408,17.567) AM60(-36.678,17.816) AM61(-37.328,17.816) AM62(-37.978,17.709) AM63(-38.628,17.709) AN1(0,18.46) AN2(-0.65,18.46) AN3(-1.3,18.498) AN4(-1.951,18.498) AN5(-2.901,18.077) AN7(-3.739,18.077) AN8(-4.303,18.402) AN10(-5.658,18.077) AN11(-6.221,18.402) AN13(-7.576,18.077) AN15(-8.14,18.402) AN17(-9.222,17.883) AN18(-9.848,18.217) AN20(-10.801,18.217) AN21(-11.753,18.217) AN22(-12.706,18.217) AN23(-13.529,18.217) AN25(-14.504,18.217) AN26(-15.456,18.217) AN28(-16.409,18.217) AN29(-17.361,18.217) AN31(-18.26,17.892) AN32(-18.824,18.217) AN33(-19.726,18.217) AN35(-20.729,18.217) AN36(-21.58,18.217) AN38(-22.634,18.217) AN39(-23.542,17.892) AN40(-24.131,18.217) AN42(-24.944,18.217) AN43(-25.897,18.217) AN45(-26.874,18.217) AN46(-27.802,18.217) AN48(-28.856,18.217) AN49(-29.757,18.217) AN51(-30.761,18.217) AN52(-31.583,18.217) AN54(-32.61,18.217) AN55(-33.562,18.217) AN57(-34.509,18.217) AN58(-35.408,18.217) AN60(-36.352,18.385) AN61(-37.003,18.385) AN62(-37.653,18.385) AN63(-38.303,18.385) AP1(0,19.21) AP2(-0.65,19.21) AP3(-1.3,19.171) AP4(-1.951,19.171) AP5(-2.901,18.727) AP7(-3.739,18.727) AP8(-4.303,19.052) AP10(-5.658,18.727) AP11(-6.221,19.052) AP13(-7.576,18.727) AP15(-8.14,19.052) AP17(-9.222,18.533) AP18(-9.848,18.867) AP20(-10.801,18.867) AP21(-11.753,18.867) AP22(-12.706,18.867) AP23(-13.529,18.867) AP25(-14.504,18.867) AP26(-15.456,18.867) AP28(-16.409,18.867) AP29(-17.361,18.867) AP31(-18.26,18.542) AP32(-18.824,18.867) AP33(-19.726,18.867) AP35(-20.729,18.867) AP36(-21.58,18.867) AP38(-22.634,18.867) AP39(-23.542,18.542) AP40(-24.131,18.867) AP42(-24.944,18.867) AP43(-25.897,18.867) AP45(-26.874,18.867) AP46(-27.802,18.867) AP48(-28.856,18.867) AP49(-29.757,18.867) AP51(-30.761,18.867) AP52(-31.583,18.867) AP54(-32.61,18.867) AP55(-33.562,18.867) AP57(-34.509,18.867) AP58(-35.408,18.867) AP60(-36.678,19.06) AP61(-37.328,19.06) AP62(-37.978,19.06) AP63(-38.628,19.06) AR5(-2.901,19.377) AR7(-3.739,19.377) AR8(-4.303,19.702) AR10(-5.658,19.377) AR11(-6.221,19.702) AR13(-7.576,19.377) AR15(-8.14,19.702) AR17(-9.222,19.184) AR18(-9.848,19.517) AR20(-10.801,19.517) AR21(-11.753,19.517) AR22(-12.706,19.517) AR23(-13.529,19.517) AR25(-14.504,19.517) AR26(-15.456,19.517) AR28(-16.409,19.517) AR29(-17.361,19.517) AR31(-18.26,19.192) AR32(-18.824,19.517) AR33(-19.726,19.517) AR35(-20.729,19.517) AR36(-21.58,19.517) AR38(-22.634,19.517) AR39(-23.542,19.192) AR40(-24.131,19.517) AR42(-24.944,19.517) AR43(-25.897,19.517) AR45(-26.874,19.517) AR46(-27.802,19.517) AR48(-28.856,19.517) AR49(-29.757,19.517) AR51(-30.761,19.517) AR52(-31.583,19.517) AR54(-32.61,19.517) AR55(-33.562,19.517) AR57(-34.509,19.517) AR58(-35.408,19.517) AT2(-0.65,19.959) AT3(-1.3,19.997) AT4(-1.951,19.997) AT5(-2.901,20.027) AT7(-3.739,20.027) AT10(-5.658,20.027) AT13(-7.576,20.027) AT35(-20.437,20.22) AT37(-22.011,20.22) AT40(-23.586,20.22) AT42(-25.161,20.22) AT43(-26.736,20.22) AT46(-28.311,20.22) AT49(-29.912,20.248) AT61(-37.003,19.634) AT62(-37.812,19.69) AU2(-0.655,20.647) AU3(-1.315,20.647) AU4(-1.976,20.647) AU6(-3.337,20.678) AU7(-4.163,20.678) AU8(-4.836,20.678) AU10(-5.661,20.678) AU11(-6.335,20.678) AU12(-7.16,20.678) AU14(-7.833,20.678) AU15(-8.659,20.678) AU16(-9.222,20.353) AU17(-9.86,20.678) AU18(-10.536,20.353) AU19(-11.105,20.678) AU20(-11.751,20.353) AU21(-12.397,20.678) AU22(-12.966,20.353) AU23(-13.642,20.678) AU24(-14.318,20.353) AU25(-14.993,20.678) AU26(-15.669,20.353) AU27(-16.238,20.678) AU28(-16.884,20.353) AU29(-17.531,20.678) AU30(-18.1,20.353) AU31(-18.775,20.678) AU33(-19.372,20.33) AU34(-19.974,20.678) AU35(-20.899,20.678) AU36(-21.549,20.678) AU37(-22.474,20.678) AU39(-23.124,20.678) AU40(-24.048,20.678) AU41(-24.699,20.678) AU42(-25.623,20.678) AU43(-26.274,20.678) AU44(-27.198,20.678) AU46(-27.848,20.678) AU47(-28.773,20.678) AU49(-29.423,20.678) AU50(-30.4,20.678) AU51(-30.98,20.353) AU52(-31.656,20.678) AU53(-32.331,20.353) AU54(-32.9,20.678) AU55(-33.547,20.353) AU56(-34.193,20.678) AU57(-34.762,20.353) AU58(-35.438,20.678) AU59(-36.002,20.353) AU60(-36.566,20.678) AU61(-37.277,20.401) AU62(-37.978,20.663) AV3(-1.321,21.308) AV4(-1.976,21.308) AV5(-2.664,21.328) AV6(-3.337,21.328) AV7(-4.163,21.328) AV8(-4.836,21.328) AV10(-5.661,21.328) AV11(-6.335,21.328) AV12(-7.16,21.328) AV14(-7.833,21.328) AV15(-8.659,21.328) AV16(-9.222,21.003) AV17(-9.86,21.328) AV18(-10.536,21.003) AV19(-11.105,21.328) AV20(-11.751,21.003) AV21(-12.397,21.328) AV22(-12.966,21.003) AV23(-13.642,21.328) AV24(-14.318,21.003) AV25(-14.993,21.328) AV26(-15.669,21.003) AV27(-16.238,21.328) AV28(-16.884,21.003) AV29(-17.531,21.328) AV30(-18.1,21.003) AV31(-18.775,21.328) AV33(-19.4,21.003) AV34(-20.024,21.328) AV35(-20.849,21.328) AV36(-21.599,21.328) AV37(-22.424,21.328) AV39(-23.173,21.328) AV40(-23.999,21.328) AV41(-24.748,21.328) AV42(-25.574,21.328) AV43(-26.323,21.328) AV44(-27.149,21.328) AV46(-27.898,21.328) AV47(-28.723,21.328) AV49(-29.473,21.328) AV50(-30.298,21.328) AV51(-30.98,21.003) AV52(-31.656,21.328) AV53(-32.331,21.003) AV54(-32.9,21.328) AV55(-33.547,21.003) AV56(-34.193,21.328) AV57(-34.762,21.003) AV58(-35.438,21.328) AV59(-36.002,21.003) AV60(-36.566,21.328) AV61(-37.302,21.051) AW4(-1.976,21.968) AW5(-2.626,21.978) AW6(-3.375,21.978) AW7(-4.125,21.978) AW8(-4.874,21.978) AW10(-5.623,21.978) AW11(-6.373,21.978) AW12(-7.122,21.978) AW14(-7.871,21.978) AW15(-8.621,21.978) AW16(-9.222,21.653) AW17(-9.86,21.978) AW18(-10.536,21.653) AW19(-11.211,21.978) AW21(-12.291,21.978) AW22(-12.966,21.653) AW23(-13.642,21.978) AW24(-14.318,21.653) AW25(-14.993,21.978) AW26(-15.669,21.653) AW27(-16.345,21.978) AW29(-17.424,21.978) AW30(-18.1,21.653) AW31(-18.775,21.978) AW33(-19.451,21.653) AW34(-20.024,21.978) AW35(-20.849,21.978) AW36(-21.599,21.978) AW37(-22.424,21.978) AW39(-23.173,21.978) AW40(-23.999,21.978) AW41(-24.748,21.978) AW42(-25.574,21.978) AW43(-26.323,21.978) AW44(-27.149,21.978) AW46(-27.898,21.978) AW47(-28.723,21.978) AW49(-29.473,21.978) AW50(-30.298,21.978) AW51(-30.98,21.653) AW52(-31.656,21.978) AW53(-32.331,21.653) AW54(-33.007,21.978) AW56(-34.087,21.978) AW57(-34.762,21.653) AW58(-35.438,21.978) AW59(-36.002,21.653) AW60(-36.566,21.978) AY6(-3.375,22.628) AY7(-4.125,22.628) AY8(-4.874,22.628) AY10(-5.623,22.628) AY11(-6.373,22.628) AY12(-7.122,22.628) AY14(-7.871,22.628) AY15(-8.621,22.628) AY16(-9.184,22.303) AY17(-9.86,22.628) AY18(-10.536,22.303) AY19(-11.211,22.628) AY21(-12.291,22.628) AY22(-12.966,22.303) AY23(-13.642,22.628) AY24(-14.318,22.303) AY25(-14.993,22.628) AY26(-15.669,22.303) AY27(-16.345,22.628) AY29(-17.424,22.628) AY30(-18.1,22.303) AY31(-18.775,22.628) AY33(-19.451,22.303) AY34(-20.024,22.628) AY35(-20.849,22.628) AY36(-21.599,22.628) AY37(-22.424,22.628) AY39(-23.173,22.628) AY40(-23.999,22.628) AY41(-24.748,22.628) AY42(-25.574,22.628) AY43(-26.323,22.628) AY44(-27.149,22.628) AY46(-27.898,22.628) AY47(-28.723,22.628) AY49(-29.473,22.628) AY50(-30.298,22.628) AY51(-30.98,22.303) AY52(-31.656,22.628) AY53(-32.331,22.303) AY54(-33.007,22.628) AY56(-34.087,22.628) AY57(-34.762,22.303) AY58(-35.438,22.628) B4(-1.922,0.65) B5(-3.138,0.643) B6(-4.119,0.643) B8(-4.891,0.643) B9(-5.716,0.643) B11(-6.697,0.643) B12(-7.469,0.643) B14(-8.294,0.643) B15(-9.275,0.643) B17(-10.047,0.643) B18(-10.872,0.643) B20(-11.853,0.643) B21(-12.272,1.196) B22(-12.625,0.643) B23(-13.451,0.643) B24(-14.023,0.975) B25(-14.714,0.65) B26(-15.277,0.975) B27(-15.84,0.65) B28(-16.531,0.975) B29(-17.221,0.65) B30(-17.785,0.975) B31(-18.348,0.65) B32(-19.038,0.975) B33(-19.729,0.65) B34(-20.292,0.975) B35(-20.855,0.65) B36(-21.546,0.975) B37(-22.236,0.65) B38(-22.8,0.975) B39(-23.363,0.65) B40(-24.053,0.975) B41(-24.744,0.65) B42(-25.307,0.975) B43(-25.87,0.65) B44(-26.561,0.975) B45(-27.251,0.65) B46(-27.815,0.975) B47(-28.378,0.65) B48(-29.068,0.975) B49(-29.759,0.65) B50(-30.322,0.975) B51(-30.885,0.65) B52(-31.576,0.975) B53(-32.266,0.65) B54(-32.83,0.975) B55(-33.393,0.65) B56(-34.083,0.975) B57(-34.774,0.65) B58(-35.337,0.975) B59(-35.9,0.65) B60(-36.665,0.66) C3(-1.302,1.302) C4(-2.118,1.272) C5(-2.772,1.196) C6(-3.776,1.196) C8(-4.538,1.196) C9(-5.351,1.196) C11(-6.354,1.196) C12(-7.116,1.196) C14(-7.929,1.196) C15(-8.932,1.196) C17(-9.694,1.196) C18(-10.507,1.196) C20(-11.51,1.196) C21(-11.891,1.786) C22(-12.678,1.786) C23(-13.085,1.196) C24(-14.051,2.032) C25(-14.714,1.3) C26(-15.277,1.626) C27(-15.84,1.3) C28(-16.558,2.032) C29(-17.221,1.3) C30(-17.785,1.626) C31(-18.348,1.3) C32(-19.066,2.032) C33(-19.729,1.3) C34(-20.292,1.626) C35(-20.855,1.3) C36(-21.573,2.032) C37(-22.236,1.3) C38(-22.8,1.626) C39(-23.363,1.3) C40(-24.081,2.032) C41(-24.744,1.3) C42(-25.307,1.626) C43(-25.87,1.3) C44(-26.588,2.032) C45(-27.251,1.3) C46(-27.815,1.626) C47(-28.378,1.3) C48(-29.07,2.032) C49(-29.759,1.3) C50(-30.322,1.626) C51(-30.885,1.3) C52(-31.578,1.991) C53(-32.266,1.3) C54(-32.83,1.626) C55(-33.393,1.3) C56(-34.085,1.991) C57(-34.774,1.3) C58(-35.337,1.626) C59(-35.9,1.3) C61(-37.003,1.237) D2(-0.65,2.075) D3(-1.3,2.037) D5(-2.678,1.842) D6(-3.369,1.786) D8(-4.157,1.786) D9(-4.944,1.786) D11(-5.852,1.786) D12(-6.735,1.786) D14(-7.522,1.786) D15(-8.43,1.786) D17(-9.313,1.786) D18(-10.1,1.786) D20(-11.008,1.786) D21(-12.235,2.423) D23(-13.377,1.786) D25(-14.714,1.951) D26(-15.277,2.276) D27(-15.84,1.951) D29(-17.221,1.951) D30(-17.785,2.276) D31(-18.348,1.951) D33(-19.729,1.951) D34(-20.292,2.276) D35(-20.855,1.951) D37(-22.236,1.951) D38(-22.8,2.276) D39(-23.363,1.951) D41(-24.744,1.951) D42(-25.307,2.276) D43(-25.87,1.951) D45(-27.251,1.951) D46(-27.815,2.276) D47(-28.378,1.951) D49(-29.759,1.951) D50(-30.322,2.276) D51(-30.885,1.951) D53(-32.266,1.951) D54(-32.83,2.276) D55(-33.393,1.951) D57(-34.774,1.951) D58(-35.337,2.276) D59(-35.9,1.951) D60(-36.678,1.801) D61(-37.328,1.801) D62(-37.978,2.035) E2(-0.65,2.725) E3(-1.3,2.687) E4(-1.951,2.687) E5(-2.602,2.619) E6(-3.554,2.619) E8(-4.507,2.619) E10(-5.459,2.619) E11(-6.412,2.619) E13(-7.364,2.619) E15(-8.317,2.619) E17(-9.269,2.619) E18(-10.222,2.619) E20(-11.174,2.619) E59(-36.027,2.647) E60(-36.678,2.647) E61(-37.328,2.647) E62(-37.978,2.685) F2(-0.65,3.474) F3(-1.3,3.512) F4(-1.951,3.512) F5(-2.602,3.269) F6(-3.554,3.269) F8(-4.507,3.269) F10(-5.459,3.269) F11(-6.412,3.269) F13(-7.364,3.269) F15(-8.317,3.269) F17(-9.269,3.269) F18(-10.222,3.269) F20(-11.174,3.269) F59(-36.027,3.472) F60(-36.678,3.472) F61(-37.328,3.472) F62(-37.978,3.434) F63(-38.628,3.434) G1(0,4.224) G2(-0.65,4.224) G3(-1.3,4.185) G4(-1.951,4.185) G5(-2.602,3.919) G6(-3.554,3.919) G8(-4.507,3.919) G10(-5.459,3.919) G11(-6.412,3.919) G13(-7.364,3.919) G15(-8.317,3.919) G17(-9.269,3.919) G18(-10.222,3.919) G20(-11.174,3.919) H5(-2.602,4.569) H6(-3.554,4.569) H8(-4.507,4.569) H10(-5.459,4.569) H11(-6.412,4.569) H13(-7.364,4.569) H15(-8.317,4.569) H17(-9.269,4.569) H18(-10.222,4.569) H20(-11.174,4.569) H59(-36.027,4.145) H60(-36.678,4.145) H61(-37.328,4.145) H62(-37.978,4.183) H63(-38.628,4.183) J1(0,4.973) J2(-0.65,4.973) J3(-1.3,5.011) J4(-1.951,5.011) J5(-2.627,5.22) J6(-3.567,5.22) J8(-4.507,5.22) J10(-5.459,5.22) J11(-6.412,5.22) J13(-7.364,5.22) J15(-8.317,5.22) J17(-9.269,5.22) J18(-10.222,5.22) J20(-11.174,5.22) J21(-12.095,4.986) J59(-36.027,4.971) J60(-36.678,4.971) J61(-37.328,4.971) J62(-37.978,4.933) J63(-38.628,4.933) K1(0,5.722) K2(-0.65,5.722) K3(-1.3,5.684) K4(-1.951,5.684) K59(-36.027,5.644) K60(-36.678,5.644) K61(-37.328,5.644) K62(-37.978,5.682) K63(-38.628,5.682) L1(0,6.471) L2(-0.65,6.471) L3(-1.3,6.51) L4(-1.951,6.51) L5(-2.637,6.338) L6(-3.287,6.338) L7(-3.937,6.338) L8(-4.587,6.338) L59(-36.027,6.469) L60(-36.678,6.469) L61(-37.328,6.469) L62(-37.978,6.431) L63(-38.628,6.431) N1(0,7.221) N2(-0.65,7.221) N3(-1.3,7.183) N4(-1.951,7.183) N5(-2.637,7.29) N6(-3.287,7.29) N7(-3.937,7.29) N8(-4.587,7.29) N59(-36.027,7.142) N60(-36.678,7.142) N61(-37.328,7.142) N62(-37.978,7.181) N63(-38.628,7.181) P1(0,7.97) P2(-0.65,7.97) P3(-1.3,8.008) P4(-1.951,8.008) P59(-36.027,7.968) P60(-36.678,7.968) P61(-37.328,7.968) P62(-37.978,7.93) P63(-38.628,7.93) R5(-2.637,8.243) R6(-3.287,8.243) R7(-3.937,8.243) R8(-4.587,8.243) T1(0,8.719) T2(-0.65,8.719) T3(-1.3,8.681) T4(-1.951,8.681) T59(-36.027,8.641) T60(-36.678,8.641) T61(-37.328,8.641) T62(-37.978,8.679) T63(-38.628,8.679) U1(0,9.469) U2(-0.65,9.469) U3(-1.3,9.507) U4(-1.951,9.507) U5(-2.637,9.195) U6(-3.287,9.195) U7(-3.937,9.195) U8(-4.587,9.195) U59(-36.027,9.467) U60(-36.678,9.467) U61(-37.328,9.467) U62(-37.978,9.428) U63(-38.628,9.428) V1(0,10.218) V2(-0.65,10.218) V3(-1.3,10.18) V4(-1.951,10.18) V5(-2.637,10.148) V6(-3.287,10.148) V7(-3.937,10.148) V8(-4.587,10.148) V59(-36.027,10.14) V60(-36.678,10.14) V61(-37.328,10.14) V62(-37.978,10.178) V63(-38.628,10.178) Y1(0,10.967) Y2(-0.65,10.967) Y3(-1.3,11.005) Y4(-1.951,11.005) Y5(-2.637,11.1) Y6(-3.287,11.1) Y7(-3.937,11.1) Y8(-4.587,11.1) Y59(-36.027,10.965) Y60(-36.678,10.965) Y61(-37.328,10.965) Y62(-37.978,10.927) Y63(-38.628,10.927)
  round 0.33 smd: AK22(-12.655,16.266) AK23(-13.529,16.266) AK25(-14.504,16.266) AK26(-15.456,16.266) AK28(-16.409,16.266) AK29(-17.311,16.266) AK32(-18.824,16.266) AK33(-19.726,16.266) AK35(-20.729,16.266) AK36(-21.58,16.266) AK38(-22.609,16.266) AK40(-24.106,16.266) AK42(-24.944,16.266) AK43(-25.897,16.266) AK45(-26.874,16.266) AK46(-27.776,16.266) AK48(-28.83,16.266) AK49(-29.732,16.266) AK51(-30.735,16.266) AK52(-31.583,16.266) AK54(-32.61,16.266) AK55(-33.562,16.266) AK57(-34.509,16.266) AK58(-35.408,16.266)
BELLW_80001-1021_204P
  round 1.092 hole 1.092 unplated: (-65.05,-4.1)
  round 1.6 hole 1.6 unplated: (1.75,-4.1)
  oval 0.356x2.007 smd: 1(0,0) 2(-0.3,-8.2) 3(-0.6,0) 4(-0.9,-8.2) 5(-1.2,0) 6(-1.5,-8.2) 7(-1.8,0) 8(-2.1,-8.2) 9(-2.4,0) 10(-2.7,-8.2) 11(-3,0) 12(-3.3,-8.2) 13(-3.6,0) 14(-3.9,-8.2) 15(-4.2,0) 16(-4.5,-8.2) 17(-4.8,0) 18(-5.1,-8.2) 19(-5.4,0) 20(-5.7,-8.2) 21(-6,0) 22(-6.3,-8.2) 23(-6.6,0) 24(-6.9,-8.2) 25(-7.2,0) 26(-7.5,-8.2) 27(-7.8,0) 28(-8.1,-8.2) 29(-8.4,0) 30(-8.7,-8.2) 31(-9,0) 32(-9.3,-8.2) 33(-9.6,0) 34(-9.9,-8.2) 35(-10.2,0) 36(-10.5,-8.2) 37(-10.8,0) 38(-11.1,-8.2) 39(-11.4,0) 40(-11.7,-8.2) 41(-12,0) 42(-12.3,-8.2) 43(-12.6,0) 44(-12.9,-8.2) 45(-13.2,0) 46(-13.5,-8.2) 47(-13.8,0) 48(-14.1,-8.2) 49(-14.4,0) 50(-14.7,-8.2) 51(-15,0) 52(-15.3,-8.2) 53(-15.6,0) 54(-15.9,-8.2) 55(-16.2,0) 56(-16.5,-8.2) 57(-16.8,0) 58(-17.1,-8.2) 59(-17.4,0) 60(-17.7,-8.2) 61(-18,0) 62(-18.3,-8.2) 63(-18.6,0) 64(-18.9,-8.2) 65(-19.2,0) 66(-19.5,-8.2) 67(-19.8,0) 68(-20.1,-8.2) 69(-20.4,0) 70(-20.7,-8.2) 71(-21,0) 72(-21.3,-8.2) 73(-24,0) 74(-24.3,-8.2) 75(-24.6,0) 76(-24.9,-8.2) 77(-25.2,0) 78(-25.5,-8.2) 79(-25.8,0) 80(-26.1,-8.2) 81(-26.4,0) 82(-26.7,-8.2) 83(-27,0) 84(-27.3,-8.2) 85(-27.6,0) 86(-27.9,-8.2) 87(-28.2,0) 88(-28.5,-8.2) 89(-28.8,0) 90(-29.1,-8.2) 91(-29.4,0) 92(-29.7,-8.2) 93(-30,0) 94(-30.3,-8.2) 95(-30.6,0) 96(-30.9,-8.2) 97(-31.2,0) 98(-31.5,-8.2) 99(-31.8,0) 100(-32.1,-8.2) 101(-32.4,0) 102(-32.7,-8.2) 103(-33,0) 104(-33.3,-8.2) 105(-33.6,0) 106(-33.9,-8.2) 107(-34.2,0) 108(-34.5,-8.2) 109(-34.8,0) 110(-35.1,-8.2) 111(-35.4,0) 112(-35.7,-8.2) 113(-36,0) 114(-36.3,-8.2) 115(-36.6,0) 116(-36.9,-8.2) 117(-37.2,0) 118(-37.5,-8.2) 119(-37.8,0) 120(-38.1,-8.2) 121(-38.4,0) 122(-38.7,-8.2) 123(-39,0) 124(-39.3,-8.2) 125(-39.6,0) 126(-39.9,-8.2) 127(-40.2,0) 128(-40.5,-8.2) 129(-40.8,0) 130(-41.1,-8.2) 131(-41.4,0) 132(-41.7,-8.2) 133(-42,0) 134(-42.3,-8.2) 135(-42.6,0) 136(-42.9,-8.2) 137(-43.2,0) 138(-43.5,-8.2) 139(-43.8,0) 140(-44.1,-8.2) 141(-44.4,0) 142(-44.7,-8.2) 143(-45,0) 144(-45.3,-8.2) 145(-45.6,0) 146(-45.9,-8.2) 147(-46.2,0) 148(-46.5,-8.2) 149(-46.8,0) 150(-47.1,-8.2) 151(-47.4,0) 152(-47.7,-8.2) 153(-48,0) 154(-48.3,-8.2) 155(-48.6,0) 156(-48.9,-8.2) 157(-49.2,0) 158(-49.5,-8.2) 159(-49.8,0) 160(-50.1,-8.2) 161(-50.4,0) 162(-50.7,-8.2) 163(-51,0) 164(-51.3,-8.2) 165(-51.6,0) 166(-51.9,-8.2) 167(-52.2,0) 168(-52.5,-8.2) 169(-52.8,0) 170(-53.1,-8.2) 171(-53.4,0) 172(-53.7,-8.2) 173(-54,0) 174(-54.3,-8.2) 175(-54.6,0) 176(-54.9,-8.2) 177(-55.2,0) 178(-55.5,-8.2) 179(-55.8,0) 180(-56.1,-8.2) 181(-56.4,0) 182(-56.7,-8.2) 183(-57,0) 184(-57.3,-8.2) 185(-57.6,0) 186(-57.9,-8.2) 187(-58.2,0) 188(-58.5,-8.2) 189(-58.8,0) 190(-59.1,-8.2) 191(-59.4,0) 192(-59.7,-8.2) 193(-60,0) 194(-60.3,-8.2) 195(-60.6,0) 196(-60.9,-8.2) 197(-61.2,0) 198(-61.5,-8.2) 199(-61.8,0) 200(-62.1,-8.2) 201(-62.4,0) 202(-62.7,-8.2) 203(-63,0) 204(-63.3,-8.2)
  rect 3.505x4.597 smd: 205(1.15,7.9) 206(-64.45,7.9)
BELLW_80148-3221_67P-T
  round 1.092 hole 1.092 unplated: (-0.75,-5.275)
  round 1.6 hole 1.6 unplated: (19.25,-5.275)
  oval 0.305x1.549 smd: 1(0,0) 2(0.25,-7.55) 3(0.5,0) 4(0.75,-7.55) 5(1,0) 6(1.25,-7.55) 7(1.5,0) 8(3.75,-7.55) 9(4,0) 10(4.25,-7.55) 11(4.5,0) 12(4.75,-7.55) 13(5,0) 14(5.25,-7.55) 15(5.5,0) 16(5.75,-7.55) 17(6,0) 18(6.25,-7.55) 19(6.5,0) 20(6.75,-7.55) 21(7,0) 22(7.25,-7.55) 23(7.5,0) 24(7.75,-7.55) 25(8,0) 26(8.25,-7.55) 27(8.5,0) 28(8.75,-7.55) 29(9,0) 30(9.25,-7.55) 31(9.5,0) 32(9.75,-7.55) 33(10,0) 34(10.25,-7.55) 35(10.5,0) 36(10.75,-7.55) 37(11,0) 38(11.25,-7.55) 39(11.5,0) 40(11.75,-7.55) 41(12,0) 42(12.25,-7.55) 43(12.5,0) 44(12.75,-7.55) 45(13,0) 46(13.25,-7.55) 47(13.5,0) 48(13.75,-7.55) 49(14,0) 50(14.25,-7.55) 51(14.5,0) 52(14.75,-7.55) 53(15,0) 54(15.25,-7.55) 55(15.5,0) 56(15.75,-7.55) 57(16,0) 58(16.25,-7.55) 59(16.5,0) 60(16.75,-7.55) 61(17,0) 62(17.25,-7.55) 63(17.5,0) 64(17.75,-7.55) 65(18,0) 66(18.25,-7.55) 67(18.5,0)
  rect 1.194x2.743 smd: 68(-1.1,-0.775) 69(19.6,-0.775)
BELLW_80149-3221_67P
  round 1.092 hole 1.092 unplated: (-0.75,-5.275)
  round 1.6 hole 1.6 unplated: (19.25,-5.275)
  oval 0.305x1.549 smd: 1(0,0) 2(0.25,-7.55) 3(0.5,0) 4(0.75,-7.55) 5(1,0) 6(1.25,-7.55) 7(1.5,0) 8(1.75,-7.55) 9(2,0) 10(2.25,-7.55) 11(2.5,0) 12(4.75,-7.55) 13(5,0) 14(5.25,-7.55) 15(5.5,0) 16(5.75,-7.55) 17(6,0) 18(6.25,-7.55) 19(6.5,0) 20(6.75,-7.55) 21(7,0) 22(7.25,-7.55) 23(7.5,0) 24(7.75,-7.55) 25(8,0) 26(8.25,-7.55) 27(8.5,0) 28(8.75,-7.55) 29(9,0) 30(9.25,-7.55) 31(9.5,0) 32(9.75,-7.55) 33(10,0) 34(10.25,-7.55) 35(10.5,0) 36(10.75,-7.55) 37(11,0) 38(11.25,-7.55) 39(11.5,0) 40(11.75,-7.55) 41(12,0) 42(12.25,-7.55) 43(12.5,0) 44(12.75,-7.55) 45(13,0) 46(13.25,-7.55) 47(13.5,0) 48(13.75,-7.55) 49(14,0) 50(14.25,-7.55) 51(14.5,0) 52(14.75,-7.55) 53(15,0) 54(15.25,-7.55) 55(15.5,0) 56(15.75,-7.55) 57(16,0) 58(16.25,-7.55) 59(16.5,0) 60(16.75,-7.55) 61(17,0) 62(17.25,-7.55) 63(17.5,0) 64(17.75,-7.55) 65(18,0) 66(18.25,-7.55) 67(18.5,0)
  rect 1.194x2.743 smd: 68(-1.1,-0.775) 69(19.6,-0.775)
BQ24715URUYR_WQFN28_4X4
  oval 0.889x0.203 smd: 1(0,0) 2(0,-0.4) 3(0,-0.8) 4(0,-1.2) 5(0,-1.6) 6(0,-2) 7(0,-2.4) 15(4.1,-2.4) 16(4.1,-2) 17(4.1,-1.6) 18(4.1,-1.2) 19(4.1,-0.8) 20(4.1,-0.4) 21(4.1,0)
  oval 0.203x0.889 smd: 8(0.85,-3.25) 9(1.25,-3.25) 10(1.65,-3.25) 11(2.05,-3.25) 12(2.45,-3.25) 13(2.85,-3.25) 14(3.25,-3.25) 22(3.25,0.85) 23(2.85,0.85) 24(2.45,0.85) 25(2.05,0.85) 26(1.65,0.85) 27(1.25,0.85) 28(0.85,0.85)
  rect 2.591x2.591 smd: 29(2.05,-1.2)
C_0402
  rect 0.508x0.559 smd: 1(0,0) 2(0.914,0)
C_0603
  rect 0.635x0.889 smd: 1(0,0) 2(1.397,0)
C_0805
  rect 0.813x1.397 smd: 1(0,0) 2(1.702,0)
C_1206
  rect 1.016x1.651 smd: 1(0,0) 2(2.667,0)
C_1808
  rect 1.041x2.311 smd: 1(0,0) 2(4.35,0)
C_APXK6R3ARA221MF451
  oval 3.15x1.6 smd: 1(0,0) 2(5.05,0)
C_B2
  rect 1.346x2.692 smd: 1(0,0) 2(-2.75,0)
C_D
  rect 2.388x2.896 smd: 1(0,0) 2(6.1,0)
C_D2
  rect 2.388x2.794 smd: 1(0,0) 2(6.4,0)
C_D3
  rect 2.388x2.794 smd: 1(0,0) 2(6.4,0)
CD3301RHHR_QFN36_6X6
  oval 0.254x1.194 smd: 1(0,0) 2(0.5,0) 3(1,0) 4(1.5,0) 5(2,0) 6(2.5,0) 7(3,0) 8(3.5,0) 9(4,0) 19(4,5.8) 20(3.5,5.8) 21(3,5.8) 22(2.5,5.8) 23(2,5.8) 24(1.5,5.8) 25(1,5.8) 26(0.5,5.8) 27(0,5.8)
  oval 1.194x0.254 smd: 10(4.9,0.9) 11(4.9,1.4) 12(4.9,1.9) 13(4.9,2.4) 14(4.9,2.9) 15(4.9,3.4) 16(4.9,3.9) 17(4.9,4.4) 18(4.9,4.9) 28(-0.9,4.9) 29(-0.9,4.4) 30(-0.9,3.9) 31(-0.9,3.4) 32(-0.9,2.9) 33(-0.9,2.4) 34(-0.9,1.9) 35(-0.9,1.4) 36(-0.9,0.9)
  rect 4.089x4.089 smd: 37(2,2.9)
CLIP_C5P5
  round 5.512 smd: 1(0,0)
CSD97374CQ4M_SON8_3P5X4P5
  oval 0.203x0.889 smd: 1(0,0) 2(0.4,0) 3(0.8,0) 6(0.8,3.5) 7(0.4,3.5) 8(0,3.5)
  custom 0.225x0.225 smd: 4(2.2,0.262) 5(2.2,3.238)
  rect 4.039x2.21 smd: 9(1.6,1.75)
DDTA114EUA-7-F_SOT323-3
  oval 0.813x0.914 smd: 1(0,0) 2(0.65,1.6) 3(-0.65,1.6)
DMN65D8LDW-7_SOT363-6
  oval 0.432x0.61 smd: 1(0,0) 2(0.65,0) 3(1.3,0) 4(1.3,1.9) 5(0.65,1.9) 6(0,1.9)
DMN65D8LW-7_SOT323-3
  oval 0.711x0.889 smd: 1(0,0) 2(-0.65,-1.9) 3(0.65,-1.9)
DMN66D0LDW-7_SOT363-6
  oval 0.432x0.61 smd: 1(0,0) 2(0.65,0) 3(1.3,0) 4(1.3,1.9) 5(0.65,1.9) 6(0,1.9)
E-T_0870K-F20C-22L_20P
  round 0.94 hole 0.94 unplated: (-1.05,2.125) (10.55,2.125)
  oval 0.254x1.143 smd: 1(0,0) 2(0.5,0) 3(1,0) 4(1.5,0) 5(2,0) 6(2.5,0) 7(3,0) 8(3.5,0) 9(4,0) 10(4.5,0) 11(5,0) 12(5.5,0) 13(6,0) 14(6.5,0) 15(7,0) 16(7.5,0) 17(8,0) 18(8.5,0) 19(9,0) 20(9.5,0)
  rect 1.295x1.397 smd: 21(10.55,0.125) 22(10.55,4.125) 23(-1.05,0.125) 24(-1.05,4.125)
E-T_4260K-Q06N-23L_6P
  oval 0.508x1.6 smd: 1(0,0) 2(-0.8,0) 3(-1.6,0) 4(-2.4,0) 5(-3.2,0) 6(-4,0)
  rect 1.194x1.702 smd: 7(-5.3,-2.25) 8(1.3,-2.25)
E-T_4280K-F04N-05L_4P
  oval 0.61x0.838 smd: 1(0,0) 2(1.2,0) 3(2.4,0) 4(3.6,0)
  rect 0.711x0.787 smd: 5(-1.15,-3.775) 6(4.75,-3.775)
E-T_6700K-Y20N-00L_20P
  oval 0.61x1.499 smd: 1(0,0) 2(-0.5,-2.8) 3(-1,0) 4(-1.5,-2.8) 5(-2,0) 6(-2.5,-2.8) 7(-3,0) 8(-3.5,-2.8) 9(-4,0) 10(-4.5,-2.8) 11(-5,0) 12(-5.5,-2.8) 13(-6,0) 14(-6.5,-2.8) 15(-7,0) 16(-7.5,-2.8) 17(-8,0) 18(-8.5,-2.8) 19(-9,0) 20(-9.5,-2.8)
  rect 0.787x1.499 smd: 21(1,0) 22(1,-2.8) 23(-10.5,0) 24(-10.5,-2.8)
E-T_6705K-Y20N-00L_20P
  oval 0.305x1.092 smd: 1(0,0) 2(-0.5,0) 3(-1,0) 4(-1.5,0) 5(-2,0) 6(-2.5,0) 7(-3,0) 8(-3.5,0) 9(-4,0) 10(-4.5,0) 11(-5,0) 12(-5.5,0) 13(-6,0) 14(-6.5,0) 15(-7,0) 16(-7.5,0) 17(-8,0) 18(-8.5,0) 19(-9,0) 20(-9.5,0)
  rect 0.991x2.007 smd: 21(2.1,-3.15) 22(-11.6,-3.15)
ECE5048-LZY_DQFN132_11X11
  oval 0.279x0.737 smd: A1(0,0) A2(0.5,0) A3(1,0) A4(1.5,0) A5(2,0) A6(2.5,0) A7(3,0) A8(3.5,0) A9(4,0) A10(4.5,0) A11(5,0) A12(5.5,0) A13(6,0) A14(6.5,0) A15(7,0) A16(7.5,0) A33(7.5,10.9) A34(7,10.9) A35(6.5,10.9) A36(6,10.9) A37(5.5,10.9) A38(5,10.9) A39(4.5,10.9) A40(4,10.9) A41(3.5,10.9) A42(3,10.9) A43(2.5,10.9) A44(2,10.9) A45(1.5,10.9) A46(1,10.9) A47(0.5,10.9) A48(0,10.9)
  oval 0.737x0.279 smd: A17(9.2,1.7) A18(9.2,2.2) A19(9.2,2.7) A20(9.2,3.2) A21(9.2,3.7) A22(9.2,4.2) A23(9.2,4.7) A24(9.2,5.2) A25(9.2,5.7) A26(9.2,6.2) A27(9.2,6.7) A28(9.2,7.2) A29(9.2,7.7) A30(9.2,8.2) A31(9.2,8.7) A32(9.2,9.2) A49(-1.7,9.2) A50(-1.7,8.7) A51(-1.7,8.2) A52(-1.7,7.7) A53(-1.7,7.2) A54(-1.7,6.7) A55(-1.7,6.2) A56(-1.7,5.7) A57(-1.7,5.2) A58(-1.7,4.7) A59(-1.7,4.2) A60(-1.7,3.7) A61(-1.7,3.2) A62(-1.7,2.7) A63(-1.7,2.2) A64(-1.7,1.7)
  oval 0.318x0.61 smd: B1(-0.25,0.855) B2(0.25,0.855) B3(0.75,0.855) B4(1.25,0.855) B5(1.75,0.855) B6(2.25,0.855) B7(2.75,0.855) B8(3.25,0.855) B9(3.75,0.855) B10(4.25,0.855) B11(4.75,0.855) B12(5.25,0.855) B13(5.75,0.855) B14(6.25,0.855) B15(6.75,0.855) B16(7.25,0.855) B17(7.75,0.855) B35(7.75,10.045) B36(7.25,10.045) B37(6.75,10.045) B38(6.25,10.045) B39(5.75,10.045) B40(5.25,10.045) B41(4.75,10.045) B42(4.25,10.045) B43(3.75,10.045) B44(3.25,10.045) B45(2.75,10.045) B46(2.25,10.045) B47(1.75,10.045) B48(1.25,10.045) B49(0.75,10.045) B50(0.25,10.045) B51(-0.25,10.045)
  oval 0.61x0.318 smd: B18(8.345,1.45) B19(8.345,1.95) B20(8.345,2.45) B21(8.345,2.95) B22(8.345,3.45) B23(8.345,3.95) B24(8.345,4.45) B25(8.345,4.95) B26(8.345,5.45) B27(8.345,5.95) B28(8.345,6.45) B29(8.345,6.95) B30(8.345,7.45) B31(8.345,7.95) B32(8.345,8.45) B33(8.345,8.95) B34(8.345,9.45) B52(-0.845,9.45) B53(-0.845,8.95) B54(-0.845,8.45) B55(-0.845,7.95) B56(-0.845,7.45) B57(-0.845,6.95) B58(-0.845,6.45) B59(-0.845,5.95) B60(-0.845,5.45) B61(-0.845,4.95) B62(-0.845,4.45) B63(-0.845,3.95) B64(-0.845,3.45) B65(-0.845,2.95) B66(-0.845,2.45) B67(-0.845,1.95) B68(-0.845,1.45)
  rect 5.105x5.105 smd: C1(3.75,5.45)
